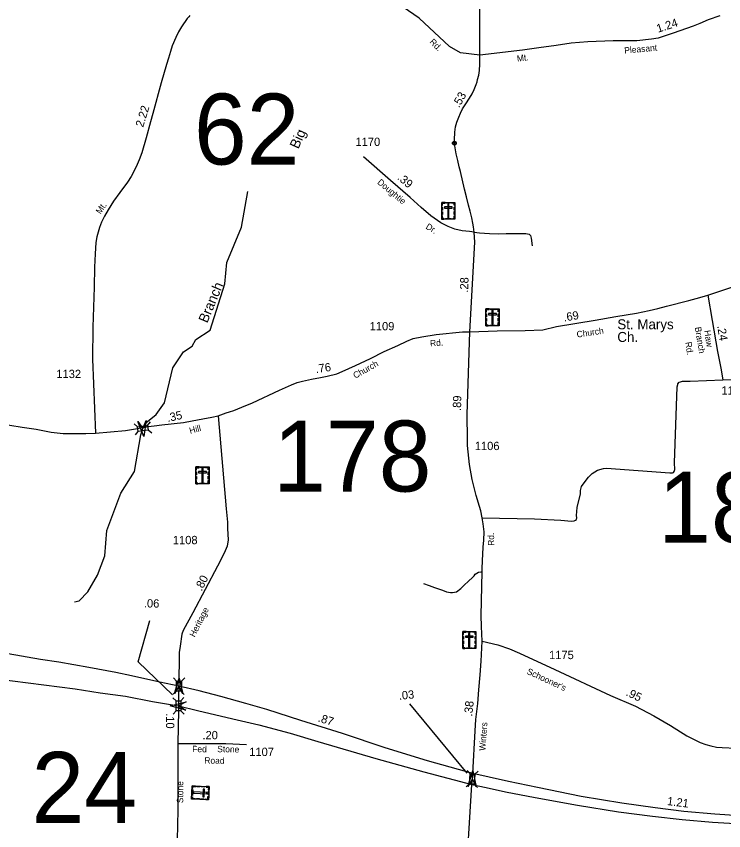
# Model space of a CAD drawing. Extents: x 2220236 to 2384410, y 720751 to 894131.
# Drawn here: x 2248753 to 2259392, y 742656 to 754902 of the extents above; entities that cross this region are included whole.
import ezdxf

# ---------------------------------------------------------------- set-up
doc = ezdxf.new("R2010")
doc.units = 0
doc.layers.add('Default', color=7, linetype='Continuous')

msp = doc.modelspace()

# ---------------------------------------------------------------- linework, layer by layer
at = {"layer": 'Default'}
for p, q in [((2259378, 749435), (2260392, 749448)), ((2250523, 748773), (2250577, 748731)), ((2250727, 748751), (2250769, 748805)), ((2250545, 748607), (2250587, 748661)), ((2250736, 748682), (2250791, 748640)), ((2251116, 744956), (2251164, 744906)), ((2251285, 744952), (2251235, 744905)), ((2251162, 744755), (2251112, 744708)), ((2251231, 744754), (2251278, 744704)), ((2251106, 744655), (2251156, 744607)), ((2251274, 744657), (2251226, 744608)), ((2251159, 744456), (2251111, 744407)), ((2251228, 744457), (2251277, 744409)), ((2255532, 743521), (2254670, 744562)), ((2255581, 743510), (2255535, 743562)), ((2255650, 743506), (2255701, 743552)), ((2255519, 743314), (2255571, 743360)), ((2255687, 743304), (2255641, 743355))]:
    msp.add_line(p, q, dxfattribs=at)
for points in [[(2255724, 754316), (2255727, 756686), (2255733, 757383), (2255745, 758031), (2255782, 758293), (2255824, 758566), (2255848, 758698), (2255873, 758858), (2255888, 759003), (2255893, 759064), (2255890, 759124), (2255895, 759206), (2255896, 759266), (2255896, 759292), (2255893, 759372), (2255895, 759482), (2255890, 759582), (2255893, 759925)], [(2255724, 754316), (2255433, 754352), (2255268, 754449), (2254811, 754875), (2254569, 755039)], [(2251364, 754912), (2251347, 754896), (2251324, 754870), (2251237, 754744), (2251194, 754666), (2251153, 754583), (2251098, 754456), (2251071, 754370), (2251041, 754274), (2251012, 754175), (2250930, 753902), (2250807, 753442), (2250772, 753313), (2250708, 753075), (2250640, 752847), (2250600, 752745), (2250570, 752673), (2250530, 752587), (2250481, 752492), (2250426, 752407), (2250308, 752251), (2250217, 752121), (2250132, 751993), (2250077, 751896), (2250034, 751804), (2250003, 751727), (2249965, 751588), (2249950, 751502), (2249941, 751329), (2249929, 751131), (2249923, 750828), (2249905, 750227), (2249900, 749744), (2249944, 748631)], [(2259331, 754911), (2259156, 754850), (2259033, 754793), (2258932, 754752), (2258633, 754649), (2258407, 754574), (2258306, 754556), (2258085, 754535), (2257729, 754535), (2257346, 754520), (2257097, 754498), (2256871, 754462), (2256609, 754430), (2256366, 754392), (2255724, 754316)], [(2255640, 751657), (2255628, 751734), (2255617, 751790), (2255603, 751871), (2255577, 751973), (2255555, 752061), (2255522, 752188), (2255495, 752302), (2255431, 752570), (2255414, 752636), (2255391, 752734), (2255369, 752836), (2255345, 752985), (2255341, 753045), (2255347, 753159), (2255358, 753238), (2255376, 753311), (2255409, 753387), (2255433, 753447), (2255464, 753508), (2255512, 753585), (2255567, 753669), (2255607, 753735), (2255638, 753801), (2255669, 753874), (2255682, 753917), (2255691, 753953), (2255708, 754016), (2255719, 754087), (2255724, 754184), (2255724, 754316)], [(2255640, 751657), (2255569, 751664), (2255456, 751677), (2255348, 751699), (2255249, 751741), (2255135, 751795), (2254988, 751899), (2254843, 752028), (2254677, 752175), (2254379, 752432), (2253974, 752788)], [(2249630, 746097), (2249696, 746112), (2249828, 746247), (2249976, 746499), (2250082, 746789), (2250112, 747172), (2250324, 747732), (2250530, 748059), (2250624, 748606), (2250658, 748705), (2250700, 748791), (2250856, 748912), (2250980, 749090), (2251109, 749615), (2251265, 749858), (2251398, 749940), (2251455, 750041), (2251670, 750184), (2251890, 750878), (2251920, 751202), (2252141, 751729), (2252237, 752265)], [(2255573, 750156), (2255651, 751505), (2255640, 751657)], [(2255640, 751657), (2255721, 751645), (2255867, 751635), (2256008, 751632), (2256118, 751637), (2256252, 751638), (2256338, 751637), (2256401, 751635), (2256418, 751636), (2256468, 751624), (2256485, 751606), (2256496, 751567), (2256510, 751448)], [(2259154, 750707), (2259516, 750827), (2259760, 750874), (2259972, 750886), (2260306, 750887), (2260620, 750884), (2260924, 750881), (2261141, 750873), (2261379, 750868), (2261508, 750865)], [(2255573, 750156), (2255984, 750174), (2256407, 750176), (2256670, 750188), (2256876, 750237), (2257461, 750331), (2257770, 750388), (2258081, 750438), (2258272, 750478), (2258402, 750510), (2258532, 750543), (2258868, 750628), (2259035, 750671), (2259154, 750707)], [(2259154, 750707), (2259217, 750329), (2259300, 749863), (2259346, 749609), (2259378, 749435)], [(2251788, 748894), (2251911, 748939), (2251959, 748954), (2252025, 748975), (2252144, 749023), (2252303, 749091), (2252710, 749281), (2252893, 749360), (2252978, 749393), (2253055, 749417), (2253192, 749445), (2253330, 749469), (2253427, 749492), (2253571, 749525), (2253656, 749562), (2253852, 749652), (2254080, 749757), (2254284, 749863), (2254491, 749954), (2254625, 750016), (2254722, 750056), (2254853, 750082), (2255067, 750115), (2255461, 750158), (2255573, 750156)], [(2255760, 745505), (2255748, 745725), (2255745, 745894), (2255759, 746547), (2255760, 746600), (2255763, 746716), (2255775, 746920), (2255783, 747025), (2255788, 747150), (2255776, 747269), (2255759, 747359), (2255737, 747466), (2255721, 747530), (2255671, 747695), (2255611, 747938), (2255571, 748164), (2255541, 748448), (2255538, 748536), (2255534, 748912), (2255573, 750156)], [(2255759, 747359), (2256544, 747347), (2256944, 747326), (2257103, 747312), (2257145, 747314), (2257164, 747323), (2257179, 747336), (2257181, 747361), (2257179, 747395), (2257186, 747516), (2257236, 747723), (2257238, 747772), (2257252, 747830), (2257309, 747908), (2257360, 747970), (2257414, 748029), (2257492, 748077), (2257585, 748102), (2257630, 748109), (2258583, 748039), (2258620, 748036), (2258639, 748043), (2258649, 748058), (2258658, 748086), (2258654, 748185), (2258692, 749331), (2258700, 749365), (2258704, 749373), (2258722, 749399), (2258743, 749407), (2258773, 749413), (2258889, 749414), (2259378, 749435)], [(2250828, 748745), (2250940, 748760), (2251267, 748795), (2251398, 748818), (2251557, 748849), (2251691, 748873), (2251788, 748894)], [(2251788, 748894), (2251908, 747494), (2251928, 747294), (2251931, 747201), (2251939, 747028), (2251924, 746936), (2251877, 746829), (2251779, 746634), (2251409, 745933), (2251263, 745664), (2251244, 745610), (2251215, 745430), (2251202, 745336), (2251197, 744829)], [(2247393, 748651), (2247562, 748687), (2247848, 748723), (2248075, 748759), (2248253, 748776), (2248421, 748773), (2248656, 748755), (2248840, 748724), (2249053, 748693), (2249275, 748650), (2249458, 748628), (2249640, 748626), (2249799, 748628), (2249944, 748631)], [(2249944, 748631), (2250395, 748676), (2250543, 748697), (2250738, 748732), (2250828, 748745)], [(2254877, 746374), (2254963, 746343), (2255041, 746315), (2255164, 746272), (2255224, 746250), (2255281, 746236), (2255315, 746238), (2255371, 746246), (2255436, 746296), (2255490, 746347), (2255555, 746407), (2255612, 746464), (2255638, 746490), (2255656, 746512), (2255702, 746543), (2255737, 746547), (2255759, 746547)], [(2251104, 744701), (2250584, 745196), (2250761, 745818)], [(2255617, 743515), (2255653, 744159), (2255666, 744328), (2255692, 744567), (2255709, 744775), (2255728, 745001), (2255743, 745207), (2255760, 745505)], [(2255760, 745505), (2255995, 745450), (2256169, 745391), (2256323, 745324), (2256851, 745080), (2257687, 744690), (2258063, 744526), (2258342, 744384), (2258589, 744239), (2258839, 744084), (2259037, 743983), (2259125, 743951), (2259200, 743930), (2259282, 743913), (2259367, 743906), (2259572, 743896), (2259727, 743900), (2259859, 743894), (2259957, 743885), (2260053, 743860), (2260157, 743815), (2260253, 743756), (2260317, 743712), (2260367, 743681)], [(2251197, 744829), (2250910, 744889), (2250483, 744983), (2250248, 745037), (2249842, 745109), (2249394, 745188), (2249119, 745229), (2248630, 745317)], [(2246271, 745217), (2247089, 745122), (2248053, 744992), (2248696, 744909), (2249640, 744787), (2250015, 744731), (2250395, 744678), (2250801, 744601), (2251191, 744531)], [(2251197, 744829), (2251191, 744688), (2251191, 744531)], [(2255617, 743515), (2254936, 743708), (2254302, 743900), (2253659, 744116), (2253030, 744315), (2252521, 744476), (2252203, 744567), (2251829, 744673), (2251502, 744761), (2251197, 744829)], [(2251191, 744531), (2251191, 744462), (2251182, 743969)], [(2251191, 744531), (2251476, 744464), (2252011, 744340), (2252402, 744246), (2252874, 744120), (2253288, 743999), (2254159, 743744), (2254881, 743539), (2255606, 743352)], [(2251182, 743969), (2251182, 742992), (2251179, 742717), (2251173, 742537), (2251174, 742389), (2251171, 742261), (2251186, 742167), (2251207, 742017), (2251238, 741882), (2251326, 741434), (2251373, 741235), (2251409, 741027), (2251434, 740898), (2251445, 740756), (2251446, 740580), (2251439, 740482), (2251382, 740089), (2251366, 739959), (2251351, 739803), (2251345, 739535)], [(2251182, 743969), (2251902, 743968), (2252217, 743954)], [(2255606, 743352), (2255617, 743515)], [(2260557, 742824), (2260370, 742831), (2260100, 742852), (2259631, 742878), (2259259, 742905), (2258790, 742947), (2258363, 743001), (2257860, 743070), (2257249, 743172), (2256590, 743304), (2256154, 743396), (2255865, 743463), (2255617, 743515)], [(2255824, 740377), (2255532, 741302), (2255513, 741416), (2255496, 741511), (2255501, 741632), (2255509, 741788), (2255606, 743352)], [(2255606, 743352), (2255818, 743306), (2256112, 743242), (2256557, 743153), (2257191, 743038), (2257809, 742942), (2258320, 742876), (2258767, 742824), (2259223, 742784), (2259649, 742761), (2260042, 742745), (2260350, 742735), (2260504, 742728), (2260582, 742727)]]:
    msp.add_lwpolyline(points, dxfattribs=at)
for points in [[(2255318, 752999), (2255318, 753000), (2255319, 753002), (2255320, 753005), (2255320, 753006), (2255321, 753008), (2255323, 753010), (2255324, 753011), (2255325, 753012), (2255327, 753014), (2255329, 753015), (2255330, 753016), (2255332, 753017), (2255333, 753017), (2255335, 753018), (2255336, 753018), (2255338, 753018), (2255339, 753019), (2255341, 753019), (2255342, 753019), (2255344, 753019), (2255346, 753018), (2255347, 753018), (2255349, 753018), (2255350, 753017), (2255352, 753016), (2255354, 753015), (2255356, 753014), (2255357, 753013), (2255358, 753012), (2255359, 753010), (2255361, 753009), (2255362, 753008), (2255363, 753006), (2255363, 753005), (2255364, 753003), (2255364, 753001), (2255365, 753000), (2255365, 752998), (2255365, 752997), (2255365, 752995), (2255365, 752993), (2255365, 752991), (2255365, 752990), (2255364, 752988), (2255364, 752986), (2255363, 752985), (2255362, 752983), (2255361, 752981), (2255360, 752980), (2255359, 752978), (2255357, 752977), (2255356, 752975), (2255354, 752974), (2255353, 752974), (2255351, 752973), (2255349, 752972), (2255347, 752971), (2255345, 752971), (2255343, 752971), (2255342, 752971), (2255340, 752971), (2255339, 752971), (2255337, 752971), (2255335, 752972), (2255334, 752972), (2255332, 752973), (2255331, 752973), (2255330, 752974), (2255328, 752975), (2255326, 752976), (2255325, 752978), (2255323, 752979), (2255322, 752980), (2255321, 752982), (2255320, 752984), (2255320, 752985), (2255319, 752986), (2255318, 752989), (2255318, 752991), (2255318, 752992), (2255318, 752994), (2255318, 752996), (2255318, 752998)], [(2255151, 752104), (2255350, 752104), (2255350, 751850), (2255151, 751850)], [(2255151, 752061), (2255162, 752061), (2255162, 752093), (2255202, 752093), (2255202, 752104), (2255151, 752104)], [(2255225, 752104), (2255276, 752104), (2255276, 752093), (2255225, 752093)], [(2255260, 752075), (2255241, 752075), (2255241, 751872), (2255260, 751872)], [(2255350, 752061), (2255338, 752061), (2255338, 752093), (2255298, 752093), (2255298, 752104), (2255350, 752104)], [(2255151, 751987), (2255151, 752030), (2255162, 752030), (2255162, 751987)], [(2255151, 751920), (2255151, 751963), (2255162, 751963), (2255162, 751920)], [(2255191, 752036), (2255191, 752017), (2255309, 752017), (2255309, 752036)], [(2255338, 751988), (2255338, 752031), (2255350, 752031), (2255350, 751988)], [(2255338, 751922), (2255338, 751965), (2255350, 751965), (2255350, 751922)], [(2255184, 751850), (2255184, 751861), (2255162, 751861), (2255162, 751902), (2255150, 751902), (2255150, 751850)], [(2255208, 751861), (2255293, 751861), (2255293, 751850), (2255208, 751850)], [(2255317, 751850), (2255317, 751861), (2255338, 751861), (2255338, 751901), (2255350, 751901), (2255350, 751850)], [(2255814, 750502), (2256013, 750502), (2256013, 750247), (2255814, 750247)], [(2255814, 750458), (2255826, 750458), (2255826, 750491), (2255866, 750491), (2255866, 750502), (2255814, 750502)], [(2255888, 750502), (2255940, 750502), (2255940, 750490), (2255888, 750490)], [(2255923, 750472), (2255905, 750472), (2255905, 750270), (2255923, 750270)], [(2256014, 750458), (2256002, 750458), (2256002, 750491), (2255962, 750490), (2255962, 750502), (2256014, 750502)], [(2255814, 750384), (2255814, 750428), (2255826, 750428), (2255826, 750384)], [(2255814, 750317), (2255814, 750360), (2255826, 750360), (2255826, 750317)], [(2255855, 750434), (2255855, 750415), (2255973, 750415), (2255973, 750434)], [(2256002, 750385), (2256002, 750429), (2256014, 750429), (2256014, 750385)], [(2256002, 750319), (2256002, 750363), (2256013, 750363), (2256013, 750319)], [(2255847, 750247), (2255847, 750259), (2255825, 750259), (2255825, 750299), (2255814, 750299), (2255814, 750247)], [(2255872, 750259), (2255957, 750259), (2255957, 750247), (2255872, 750247)], [(2255980, 750247), (2255980, 750259), (2256002, 750259), (2256002, 750299), (2256013, 750299), (2256013, 750247)], [(2250577, 748731), (2250727, 748751), (2250736, 748681), (2250587, 748661)], [(2250706, 748826), (2250673, 748585), (2250581, 748810), (2250658, 748705)], [(2251452, 748125), (2251651, 748125), (2251651, 747871), (2251452, 747871)], [(2251452, 748082), (2251463, 748082), (2251463, 748114), (2251504, 748114), (2251504, 748125), (2251452, 748125)], [(2251526, 748125), (2251578, 748125), (2251578, 748114), (2251526, 748114)], [(2251651, 748082), (2251640, 748082), (2251640, 748114), (2251599, 748114), (2251599, 748125), (2251651, 748125)], [(2251452, 748008), (2251452, 748051), (2251463, 748051), (2251463, 748008)], [(2251493, 748057), (2251493, 748039), (2251611, 748039), (2251611, 748057)], [(2251561, 748096), (2251542, 748096), (2251542, 747893), (2251561, 747893)], [(2251640, 748009), (2251640, 748052), (2251651, 748052), (2251651, 748009)], [(2251452, 747941), (2251452, 747984), (2251463, 747984), (2251463, 747941)], [(2251485, 747871), (2251485, 747882), (2251463, 747882), (2251463, 747923), (2251452, 747923), (2251452, 747871)], [(2251509, 747882), (2251594, 747882), (2251594, 747871), (2251509, 747871)], [(2251618, 747871), (2251618, 747882), (2251640, 747882), (2251640, 747923), (2251651, 747923), (2251651, 747871)], [(2251640, 747943), (2251640, 747986), (2251651, 747986), (2251651, 747943)], [(2255466, 745651), (2255665, 745651), (2255665, 745397), (2255466, 745397)], [(2255466, 745608), (2255477, 745608), (2255477, 745640), (2255518, 745640), (2255518, 745651), (2255466, 745651)], [(2255466, 745534), (2255466, 745577), (2255477, 745577), (2255477, 745534)], [(2255507, 745583), (2255507, 745564), (2255625, 745564), (2255625, 745583)], [(2255540, 745651), (2255592, 745651), (2255592, 745640), (2255540, 745640)], [(2255575, 745622), (2255556, 745622), (2255556, 745419), (2255575, 745419)], [(2255665, 745608), (2255654, 745608), (2255654, 745640), (2255613, 745640), (2255613, 745651), (2255665, 745651)], [(2255654, 745535), (2255654, 745578), (2255665, 745578), (2255665, 745535)], [(2255466, 745467), (2255466, 745510), (2255477, 745510), (2255477, 745467)], [(2255499, 745397), (2255499, 745408), (2255477, 745408), (2255477, 745449), (2255466, 745449), (2255466, 745397)], [(2255632, 745397), (2255632, 745408), (2255654, 745408), (2255654, 745448), (2255665, 745448), (2255665, 745397)], [(2255654, 745469), (2255654, 745512), (2255665, 745512), (2255665, 745469)], [(2255523, 745408), (2255608, 745408), (2255608, 745397), (2255523, 745397)], [(2251130, 744718), (2251201, 744951), (2251256, 744714), (2251197, 744829)], [(2251235, 744905), (2251231, 744754), (2251160, 744755), (2251164, 744906)], [(2251304, 744467), (2251069, 744532), (2251305, 744594), (2251191, 744531)], [(2251226, 744608), (2251228, 744457), (2251158, 744456), (2251156, 744607)], [(2255544, 743323), (2255617, 743555), (2255670, 743317), (2255612, 743434)], [(2255571, 743360), (2255580, 743510), (2255651, 743506), (2255641, 743355)], [(2251653, 743319), (2251644, 743120), (2251390, 743131), (2251399, 743330)], [(2251407, 743272), (2251404, 743187), (2251392, 743188), (2251396, 743273)], [(2251397, 743297), (2251409, 743297), (2251410, 743319), (2251450, 743317), (2251450, 743328), (2251399, 743330)], [(2251619, 743211), (2251620, 743230), (2251417, 743239), (2251416, 743220)], [(2251468, 743327), (2251512, 743325), (2251511, 743314), (2251468, 743316)], [(2251536, 743324), (2251579, 743322), (2251578, 743311), (2251535, 743313)], [(2251583, 743281), (2251564, 743282), (2251559, 743164), (2251578, 743164)], [(2251610, 743321), (2251609, 743309), (2251641, 743308), (2251639, 743268), (2251651, 743267), (2251653, 743319)], [(2251650, 743245), (2251647, 743193), (2251636, 743194), (2251638, 743245)], [(2251391, 743164), (2251403, 743164), (2251402, 743142), (2251442, 743140), (2251442, 743129), (2251390, 743131)], [(2251462, 743139), (2251506, 743138), (2251505, 743126), (2251462, 743128)], [(2251528, 743136), (2251572, 743135), (2251571, 743123), (2251528, 743125)], [(2251601, 743122), (2251601, 743133), (2251633, 743132), (2251635, 743172), (2251646, 743172), (2251644, 743120)]]:
    msp.add_lwpolyline(points, close=True, dxfattribs=at)
for radius in [28.8, 23.4]:
    msp.add_circle((2255341, 752995), radius, dxfattribs=at)

# ---------------------------------------------------------------- texts
for s, height, rotation, p in [('1.24', 125, 17.9455, (2258404, 754654)), ('Rd.', 95, 314.8847, (2254960, 754510)), ('Pleasant', 95, 5.4959, (2257901, 754339)), ('Mt.', 95, 6.5868, (2256287, 754220)), ('.53', 125, 60.5466, (2255412, 753517)), ('2.22', 125, 72.6659, (2250660, 753226)), ('Big', 150, 65.6713, (2252994, 752898)), ('Doughtie', 95, 320.0446, (2254174, 752392)), ('.39', 125, 319.1576, (2254474, 752460)), ('Mt.', 95, 55.6229, (2250019, 751919)), ('Dr.', 95, 328.3208, (2254901, 751715)), ('.28', 125, 88.0599, (2255547, 750744)), ('Branch', 150, 67.2358, (2251624, 750280)), ('.69', 125, 10.1436, (2256992, 750310)), ('Church', 95, 8.5292, (2257187, 750070)), ('Branch', 95, 279.179, (2258957, 750224)), ('.24', 125, 279.179, (2259293, 750245)), ('Haw', 95, 279.179, (2259097, 750174)), ('Rd.', 95, 3.7427, (2254978, 749938)), ('Rd.', 95, 279.179, (2258812, 749999)), ('Church', 95, 29.3682, (2253851, 749450)), ('.76', 125, 8.0375, (2253262, 749537)), ('.89', 125, 88.6648, (2255441, 748966)), ('.35', 125, 12.5674, (2251031, 748800)), ('Hill', 95, 15.2481, (2251369, 748622)), ('Rd.', 95, 90.5059, (2255940, 746940)), ('.80', 125, 62.7485, (2251539, 746250)), ('.06', 125, 359.2367, (2250671, 746013)), ('Heritage', 95, 63.0024, (2251435, 745558)), ("Schooner's", 95, 335.1753, (2256422, 745018)), ('.03', 125, 5.6639, (2254511, 744623)), ('.95', 125, 334.4915, (2257912, 744694)), ('.38', 125, 83.7488, (2255608, 744371)), ('.10', 125, 270.1473, (2251004, 744423)), ('.87', 125, 342.4931, (2253281, 744301)), ('Winters', 95, 85.7283, (2255807, 743855)), ('.20', 125, 359.933, (2251552, 744031)), ('Fed', 95, 359.0207, (2251398, 743838)), ('Stone', 95, 359.0207, (2251774, 743837)), ('Road', 95, 359.0207, (2251580, 743666)), ('Stone', 95, 89.5293, (2251262, 743069)), ('1.21', 125, 352.7514, (2258535, 743043))]:
    msp.add_text(s, height=height, rotation=rotation, dxfattribs=at).set_placement(p)
for s, height, p in [('62', 1066.3, (2251425, 752673)), ('1170', 125, (2253854, 752952)), ('St. Marys', 150, (2257792, 750196)), ('1109', 125, (2254067, 750180)), ('Ch.', 150, (2257792, 750005)), ('1132', 125, (2249355, 749462)), ('1169', 125, (2259357, 749213)), ('178', 1066.3, (2252617, 747756)), ('1106', 125, (2255648, 748379)), ('180', 1066.3, (2258407, 746986)), ('1108', 125, (2251107, 746964)), ('1175', 125, (2256765, 745236)), ('24', 1066.3, (2248982, 742774)), ('1107', 125, (2252256, 743779))]:
    msp.add_text(s, height=height, dxfattribs=at).set_placement(p)

doc.saveas('drawing.dxf')
